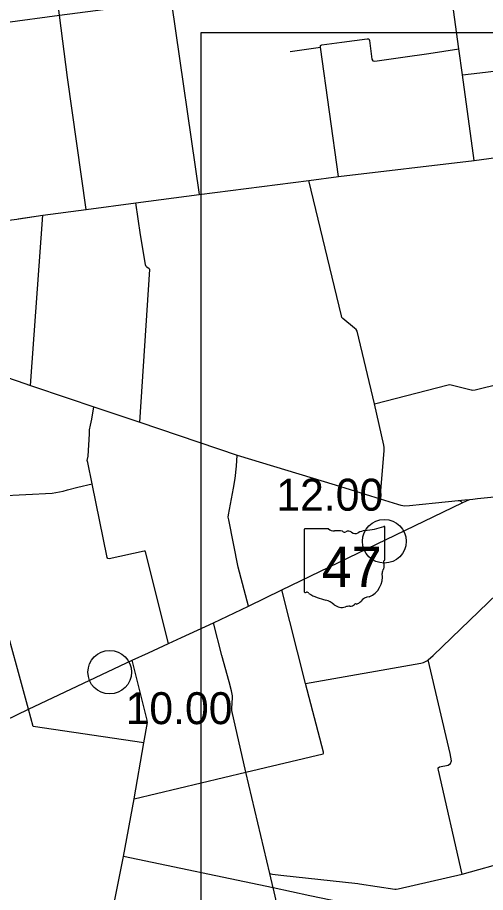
# Model space of a CAD drawing. Extents: x 1659811 to 1934326, y 644115 to 934867.
# Drawn here: x 1723269 to 1739381, y 870379 to 900512 of the extents above; entities that cross this region are included whole.
import ezdxf

# ---------------------------------------------------------------- set-up
doc = ezdxf.new("R2010")
doc.units = 0
for name, color, linetype in [('Default', 7, 'Continuous'), ('GM_X_County_Road', 7, 'Continuous'), ('GM_X_State_Route', 7, 'Continuous'), ('GM_X_State_Shield', 7, 'Continuous'), ('GM_X_Township', 7, 'Continuous'), ('GM_X_Township_Road', 7, 'Continuous'), ('SC_Scratch1', 7, 'Continuous')]:
    doc.layers.add(name, color=color, linetype=linetype)

msp = doc.modelspace()

# ---------------------------------------------------------------- linework, layer by layer
at = {"layer": 'Default'}
for centre in [(1735898, 882474), (1726443, 877966)]:
    msp.add_circle(centre, 750, dxfattribs=at)
at = {"layer": 'GM_X_County_Road'}
for points in [[(1725630, 893897), (1724990, 898451), (1724709, 900587), (1724026, 906020)], [(1738987, 895592), (1738584, 898536), (1738461, 899435), (1737736, 904736)], [(1718117, 899769), (1720962, 900082), (1724709, 900587), (1728076, 901028), (1728466, 901079), (1728522, 901084), (1728556, 901068), (1728576, 901004), (1729525, 894413)], [(1734325, 895035), (1733701, 899487), (1733705, 899545), (1733743, 899566), (1734440, 899664), (1735307, 899781), (1735363, 899773), (1735384, 899716), (1735473, 899074), (1735505, 899022), (1735568, 899003), (1736536, 899143), (1737427, 899276), (1738461, 899435)], [(1738584, 898536), (1739182, 898601), (1739853, 898686), (1740378, 898763), (1740858, 898841), (1741119, 898865), (1741748, 898940), (1741980, 899000), (1742080, 899037), (1742196, 899034), (1743242, 898979), (1743536, 899005), (1744035, 899052)], [(1723292, 893576), (1724146, 893710), (1725630, 893897), (1727338, 894125), (1729525, 894413), (1733294, 894900), (1734325, 895035), (1738987, 895592), (1740005, 895724), (1745121, 896342), (1750363, 896999), (1754204, 897454), (1758488, 897881), (1759557, 897996), (1760199, 898071)], [(1735755, 883939), (1735891, 885600), (1735890, 885698), (1735876, 885785), (1735563, 887203), (1734958, 889710), (1734932, 889765), (1734875, 889817), (1734465, 890149), (1734438, 890182), (1734418, 890236), (1733294, 894900)], [(1713704, 892393), (1718862, 893030), (1720453, 893227), (1723246, 893569), (1723292, 893576)], [(1722338, 888307), (1723256, 887994), (1723718, 887841), (1725016, 887404), (1725901, 887104), (1727481, 886571), (1730833, 885445), (1734209, 884414), (1735755, 883939), (1736346, 883756), (1736462, 883720), (1736534, 883705), (1736604, 883697), (1736764, 883710), (1737657, 883797), (1738438, 883875), (1738462, 883877), (1738479, 883875), (1738504, 883868), (1738525, 883857), (1738544, 883843), (1738558, 883829), (1738571, 883809), (1738576, 883798)], [(1738438, 883875), (1738668, 883899), (1738837, 883912)], [(1733187, 877571), (1737150, 878276), (1737245, 878303), (1737381, 878368), (1737407, 878391), (1737575, 878543), (1739787, 880664), (1739815, 880691), (1739867, 880705), (1742487, 881318)], [(1733187, 877571), (1732371, 880802)], [(1732077, 870509), (1732070, 870541), (1731954, 871032), (1731130, 874524), (1730644, 876642), (1730644, 876722), (1730675, 877087), (1730676, 877157), (1730639, 877323), (1730554, 877639), (1730306, 878542), (1730019, 879665)], [(1727621, 875533), (1727742, 876237), (1727738, 876269), (1727732, 876311), (1727688, 876496), (1727222, 878378)], [(1731130, 874524), (1733788, 875158), (1733808, 875172), (1733806, 875216), (1733187, 877571)], [(1726360, 868808), (1726920, 871614), (1727283, 873606), (1727621, 875531), (1727621, 875533)], [(1731954, 871032), (1732048, 871006), (1732333, 870975), (1734986, 870691), (1735044, 870680), (1736259, 870493), (1736303, 870497), (1736375, 870510), (1738576, 871010), (1740218, 871469), (1740470, 871543), (1743406, 872185), (1744468, 872427), (1746023, 872748), (1746071, 872757), (1746137, 872769), (1748178, 872881), (1748242, 872881), (1748291, 872896), (1749882, 873287), (1749926, 873301), (1749991, 873340), (1750808, 873862)], [(1732080, 863981), (1732694, 866964), (1732757, 867364), (1732761, 867447), (1732751, 867554), (1732077, 870509)]]:
    msp.add_lwpolyline(points, dxfattribs=at)
at = {"layer": 'GM_X_State_Route'}
for points in [[(1728920, 879163), (1730019, 879665), (1731219, 880243), (1732371, 880802), (1738576, 883798), (1738724, 883870), (1738785, 883895), (1738837, 883912), (1738941, 883928), (1739105, 883944), (1742448, 884281), (1743638, 884403)], [(1727775, 878635), (1728470, 878957), (1728920, 879163)], [(1714441, 875950), (1714876, 875868), (1716715, 875507), (1718937, 875074), (1719718, 874921), (1719850, 874896), (1719926, 874891), (1719984, 874897), (1720031, 874907), (1720109, 874940), (1720199, 874981), (1720556, 875166), (1721488, 875640), (1722846, 876301), (1723650, 876687), (1727222, 878378), (1727775, 878635)]]:
    msp.add_lwpolyline(points, dxfattribs=at)
at = {"layer": 'GM_X_State_Shield'}
for p, q in [((1735920, 881847), (1735920, 882952)), ((1733135, 882864), (1733135, 880750)), ((1733978, 882900), (1733163, 882900)), ((1735919, 881847), (1735920, 881847))]:
    msp.add_line(p, q, dxfattribs=at)
for centre, radius, start, end in [((1734928, 885781), 2953, 275.8445, 288.9065), ((1735889, 882957), 31, 351.8621, 97.738), ((1733167, 882868), 32.3, 98.1301, 188.1301), ((1734172, 883145), 313, 231.6195, 271.1119), ((1734276, 881714), 1123, 80.4867, 94.9883), ((1734531, 882879), 90.3, 219.7921, 297.1024), ((1734663, 882635), 188, 54.4667, 119.1411), ((1734906, 882970), 226, 233.8562, 294.8282), ((1735304, 882255), 594, 97.3462, 120.7689), ((1735912, 881766), 48, 107.944, 210.337), ((1735607, 881626), 288, 340.033, 23.6496), ((1735887, 881843), 33.2, 289.6038, 7.7341), ((1736031, 881384), 210, 136.8065, 186.9296), ((1735093, 881244), 739, 292.3089, 8.9858), ((1733167, 880746), 32.5, 171.9584, 258.3066), ((1733172, 880962), 248, 267.339, 280.6039), ((1733223, 880629), 89.5, 29.7484, 93.2717), ((1734354, 882527), 2132, 240.4129, 257.1985), ((1735405, 880157), 404, 94.4031, 142.5768), ((1733718, 879801), 667, 47.1842, 75.836), ((1734440, 880618), 423, 230.7004, 286.2918), ((1734684, 879887), 348, 85.6951, 111.2099), ((1734715, 880460), 226, 268.777, 315.5493), ((1734919, 880255), 63.5, 65.7517, 132.6484), ((1734892, 880546), 239, 282.8732, 323.2771)]:
    msp.add_arc(centre, radius, start, end, dxfattribs=at)
at = {"layer": 'GM_X_Township'}
for points in [[(1723246, 893569), (1724146, 893710), (1725630, 893897), (1727338, 894125), (1729525, 894413), (1733294, 894900), (1734325, 895035), (1738987, 895592), (1740005, 895724), (1745121, 896342), (1750351, 896987), (1754204, 897454), (1758488, 897881), (1759557, 897996), (1760281, 898058)], [(1759690, 868390), (1757009, 867717), (1756406, 870029), (1756359, 870081), (1756301, 870104), (1756215, 870095), (1753792, 869566), (1753714, 869562), (1751538, 869063), (1745564, 867790), (1742701, 867183), (1739485, 867962), (1739772, 868932), (1733328, 870264), (1732070, 870541), (1726920, 871614), (1727283, 873606), (1727621, 875531), (1723811, 876096), (1723650, 876687), (1722695, 880187)], [(1721338, 869100), (1725899, 868306), (1726156, 868250), (1726200, 868244), (1726230, 868258), (1726268, 868305), (1726360, 868808), (1726920, 871614)]]:
    msp.add_lwpolyline(points, dxfattribs=at)
at = {"layer": 'GM_X_Township_Road'}
for points in [[(1732657, 899341), (1733701, 899487)], [(1727481, 886571), (1727829, 891831), (1727800, 891855), (1727724, 891912), (1727698, 891942), (1727677, 891992), (1727534, 892835), (1727503, 893032), (1727338, 894125)], [(1723718, 887841), (1724146, 893710)], [(1735563, 887203), (1738100, 887865), (1738150, 887871), (1738194, 887863), (1738886, 887686), (1738924, 887680), (1739020, 887691), (1741676, 888343)], [(1728470, 878957), (1727679, 882107), (1727661, 882129), (1727629, 882136), (1726419, 881870), (1726375, 881876), (1726359, 881916), (1725834, 884447), (1725686, 885186), (1725667, 885256), (1725696, 885404), (1725746, 886179), (1725753, 886312), (1725784, 886474), (1725826, 886684), (1725901, 887104)], [(1731219, 880243), (1730867, 881580), (1730543, 883208), (1730527, 883300), (1730538, 883386), (1730706, 884307), (1730762, 884639), (1730814, 885065), (1730833, 885445)], [(1722074, 884043), (1722640, 884043), (1724462, 884128), (1724843, 884196), (1724988, 884250), (1725347, 884335), (1725834, 884447)], [(1738576, 871010), (1737760, 874587), (1737748, 874643), (1737756, 874675), (1737797, 874707), (1738097, 874768), (1738178, 874818), (1738212, 874913), (1738162, 875160), (1737407, 878391)], [(1727283, 873606), (1731130, 874524)]]:
    msp.add_lwpolyline(points, dxfattribs=at)
at = {"layer": 'SC_Scratch1'}
msp.add_lwpolyline([(1729596, 899996), (1925846, 899996), (1925846, 765496), (1729596, 765496)], close=True, dxfattribs=at)

# ---------------------------------------------------------------- texts
at = {"layer": 'Default'}
for s, p in [('12.00', (1732179, 883528)), ('10.00', (1726990, 876176))]:
    msp.add_text(s, height=1100, dxfattribs=at).set_placement(p)
at = {"layer": 'GM_X_State_Shield'}
msp.add_text('47', height=1392.2, dxfattribs=at).set_placement((1733740, 880899))

doc.saveas('drawing.dxf')
